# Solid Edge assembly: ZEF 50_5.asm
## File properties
Title: Zylinder
Author: ahadarics
Template: iso metric assembly.asm
Last saved by: ahadarics
Revision: 2
Application: Solid Edge
Username: ahadarics
Dokumentum tartalom típus: 1
Document Number: ZEF 50/5
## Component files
Profilrohr.par
Kolbenstange.par
Kit_1.par
Kit_2.par
Mutter.par
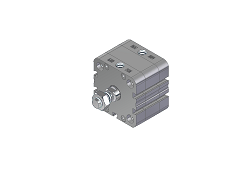
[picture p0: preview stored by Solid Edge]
